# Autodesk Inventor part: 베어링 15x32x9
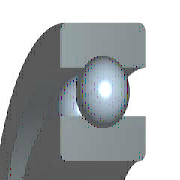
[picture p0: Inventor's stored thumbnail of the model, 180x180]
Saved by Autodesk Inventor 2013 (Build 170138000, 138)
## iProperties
IsCustomPart: 0
Created: 2012-02
Part Number: 베어링 15x32x9
Material: 강철, 연강
Description: 깊은 그루브 볼 베어링
Document SubType Name: Modeling
Standard: KS B 2023
Designer: mduedu
Standards Organization: KS
Language: ko-KR
Size Designation: 6002 - 15 x 32 x 9
Categories: <MemberInstance><Categories><Category DisplayName="샤프트 부품" InternalName="7f7aeb1f-a693-4053-b835-cee3144e0d98" Mnemonic="SHFT"><Category DisplayName="베어링" Inter
Density: 1 g/cm^3
Author: mduedu
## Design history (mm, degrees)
sketch "스케치" dims "d0" = 4.42 (= -0.26 x WD + 0.26 x BD)
  geometry: L1 (2.29, 11.75)-(6.71, 11.75); L2 (4.5, 11.75)-(4.5, 9.54); L3 (4.5, 11.75)-(4.5, 13.96); L4 (2.858, 10.271)-(0, 10.271); L5 (0, 7.5)-(9, 7.5); L6 (2.858, 13.229)-(0, 13.229); L7 (0, 16)-(9, 16); L8 (9, 7.5)-(9, 10.271); L9 (6.142, 10.271)-(9, 10.271); L10 (6.142, 13.229)-(9, 13.229); L11 (9, 16)-(9, 13.229); L12 (-1.4, 0)-(8.4, 0) reference; L13 (0, -0.3)-(0, 5.3) reference
  constraints: 22 end point, 4 point on line, 2 collinear, 2 perpendicular, 2 symmetric about line, 1 midpoint, 1 parallel, 14 other
  dimensions: "d9" = 15 diameter of L5 L12 (= WD); "d11" = 32 diameter of L7 L12 (= BD); "d12" = 9 distance between parallel lines of L8 L13 (= KB); "d13" = 20.542 diameter of L9 L12 (= 0.326 x BD + 0.674 x WD)
revolve "본체" stored, may be unused: angle "d6" = 90 deg
revolve "볼" stored, may be unused: angle "d7" = 90 deg
pattern_circular "IDS_ARRAYBALL[SIMPL:T]" dims angle "d3" = 360 deg
body "Solid1"
fillet "모깎기1" dims "d1" = 0.3 (= KRS)
other parameters: "WD" = 15 [user parameter; used in 5 equation terms], "BD" = 32 [user parameter; used in 5 equation terms], "KB" = 9 [user parameter; used in 1 equation term], "KRS" = 0.3 [user parameter; used in 1 equation term], "d4" = 0, "d5" = 0, "d8" = 0, "d14" = 0, "d15" = 0, "BBA" = 0 [user parameter], "BC0" = 2850000 [user parameter], "BC" = 5590000 [user parameter], "BR" = 16 (= 0.5 x BD) [user parameter], "WR" = 7.5 (= 0.5 x WD) [user parameter]
